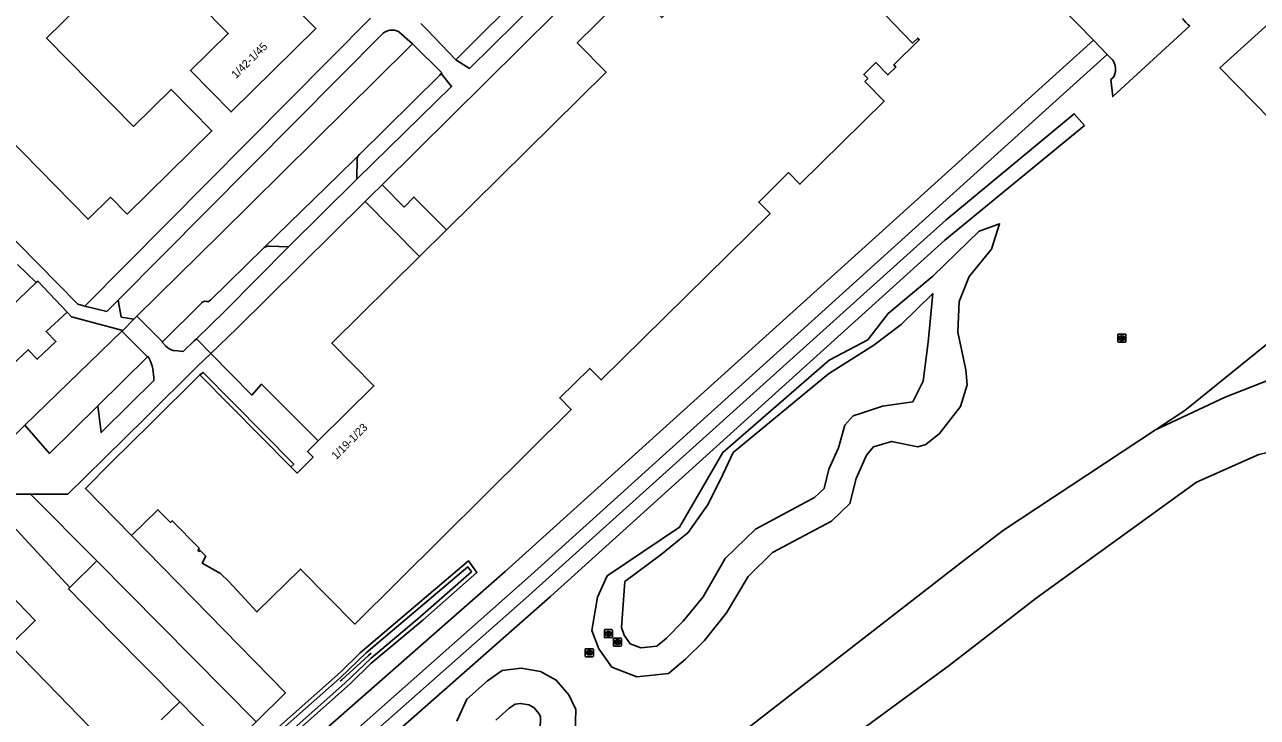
# Model space of a CAD drawing. Extents: x 162791 to 163827, y 385795 to 386523.
# Drawn here: x 162989.1 to 163143.1, y 385940.4 to 386026.9 of the extents above; entities that cross this region are included whole.
import ezdxf

# ---------------------------------------------------------------- set-up
doc = ezdxf.new("R2010")
doc.units = 0
for name, color, linetype in [('IMGEO_Duiker', 7, 'Continuous'), ('IMGEO_Erf', 7, 'Continuous'), ('IMGEO_Grasland_overig', 7, 'Continuous'), ('IMGEO_Groenvoorziening', 7, 'Continuous'), ('IMGEO_Hek', 7, 'Continuous'), ('IMGEO_Loofbos', 7, 'Continuous'), ('IMGEO_Meer_plas_ven_vijver', 7, 'Continuous'), ('IMGEO_Pand', 7, 'Continuous'), ('IMGEO_Pand_nummerreeks', 7, 'Continuous'), ('IMGEO_Parkeervlak_open', 7, 'Continuous'), ('IMGEO_Rijbaan_lokaal_gesloten', 7, 'Continuous'), ('IMGEO_Rijbaan_lokaal_open', 7, 'Continuous'), ('IMGEO_Rioolput', 7, 'Continuous'), ('IMGEO_Rivier', 7, 'Continuous'), ('IMGEO_Terreindeel_open', 7, 'Continuous'), ('IMGEO_Voetpad_halfverhard', 7, 'Continuous'), ('IMGEO_Voetpad_open', 7, 'Continuous'), ('IMGEO_Waterloop', 7, 'Continuous'), ('IMGEO_Woonerf_gesloten', 7, 'Continuous'), ('IMGEO_Woonerf_open', 7, 'Continuous')]:
    doc.layers.add(name, color=color, linetype=linetype)

msp = doc.modelspace()

# ---------------------------------------------------------------- linework, layer by layer
at = {"layer": 'IMGEO_Duiker'}
msp.add_lwpolyline([(163032.39, 385948.39), (163032.06, 385948.09), (163028.71, 385945.05), (163028.51, 385944.87)], dxfattribs=at)
at = {"layer": 'IMGEO_Erf'}
msp.add_lwpolyline([(163029.78, 385944.56), (163016.33, 385932.62), (163015.69, 385932.14), (163014.74, 385932.48), (163014.13, 385933.23), (163028.55, 385946.01), (163031.02, 385948.44), (163044.54, 385959.92), (163045.58, 385958.47), (163038.86, 385952.52), (163032.36, 385947.07), (163029.78, 385944.56)], dxfattribs=at)
at = {"layer": 'IMGEO_Grasland_overig'}
for points in [[(163206.68, 386083.38), (163206.37, 386083.1), (163138.45, 386021.55), (163159.54, 386000), (163159.93, 385999.61)], [(163106.02, 385979.22), (163106.86, 385981.92), (163106.68, 385983.79), (163105.69, 385988.52), (163105.84, 385992.35), (163107.1, 385995.47), (163109.92, 385998.89), (163110.92, 386002.06), (163108.35, 386001.11), (163102.57, 385995.52), (163096.98, 385990.84), (163094.46, 385987.56), (163089.63, 385985), (163076.31, 385973.48), (163070.9, 385964.13), (163061.89, 385958.05), (163060.67, 385955.36), (163059.97, 385951.22), (163060.84, 385948.94), (163062.45, 385946.64), (163065.6, 385945.4), (163069.55, 385945.84), (163071.68, 385947.62), (163074.04, 385949.98), (163076.8, 385953.4), (163079.48, 385957.98), (163082.54, 385960.98), (163089.9, 385964.89), (163092.2, 385967.07), (163092.98, 385970.2), (163094.27, 385973.14), (163095.16, 385974.15), (163097.41, 385974.84), (163100.69, 385974.17), (163101.69, 385974.44), (163103.39, 385975.82), (163106.02, 385979.22)], [(163040.43, 385899.61), (163044.54, 385903.54), (163046.78, 385907.18), (163047.56, 385909.89), (163047.5, 385912), (163047.85, 385913.76), (163049.18, 385914.93), (163052.8, 385917.43), (163058.52, 385922.26), (163075.19, 385935.93), (163079.12, 385938.74), (163105.9, 385959.53), (163111.4, 385963.76), (163130.4, 385976.29)], [(163004.99, 385938.91), (163001.1, 385935.13), (162993.27, 385943.2), (162987.27, 385949.39), (162990.42, 385952.45), (162984.93, 385958.1), (162984.82, 385958.21), (162984.99, 385958.38), (162983.58, 385959.83), (162983.68, 385959.93), (162982.32, 385961.34), (162982.74, 385961.74), (162981.36, 385963.16), (162980.71, 385967.36)], [(163057.86, 385938.35), (163057.95, 385941.32), (163057.1, 385943.18), (163055.52, 385945.02), (163053.56, 385946.09), (163051.15, 385946.52), (163048.76, 385946.2), (163046.92, 385944.94), (163044.36, 385942.63), (163043.1, 385939.87)]]:
    msp.add_lwpolyline(points, dxfattribs=at)
at = {"layer": 'IMGEO_Groenvoorziening'}
msp.add_lwpolyline([(162986.64, 385968.27), (162986.63, 385966.43), (162987.09, 385965.94), (162986.55, 385965.43), (162994.73, 385956.59)], dxfattribs=at)
at = {"layer": 'IMGEO_Hek'}
msp.add_lwpolyline([(163159.93, 385999.61), (163159.54, 386000), (163138.45, 386021.55), (163206.37, 386083.1), (163209.63, 386080.99), (163212.23, 386083.36)], dxfattribs=at)
at = {"layer": 'IMGEO_Loofbos'}
for points in [[(163159.93, 385999.61), (163134.06, 385978.71), (163130.4, 385976.29)], [(163130.4, 385976.29), (163139.09, 385980.37), (163147.79, 385983.78), (163156.15, 385986.14), (163163.03, 385986.86), (163172.38, 385986.5)]]:
    msp.add_lwpolyline(points, dxfattribs=at)
at = {"layer": 'IMGEO_Meer_plas_ven_vijver'}
for points in [[(163063.65, 385951.58), (163064.1, 385957.33), (163068.63, 385960.73), (163071.98, 385963.45), (163074.43, 385966.89), (163076.06, 385970.15), (163077.61, 385973.44), (163089.53, 385983.31), (163095.2, 385986.88), (163098.61, 385989.48), (163102.55, 385993.33), (163102, 385987.26), (163101.37, 385982.37), (163100.06, 385979.79), (163096.29, 385979.25), (163093.67, 385978.39), (163092.62, 385978.05), (163091.57, 385976.87), (163090.77, 385974.04), (163089.59, 385971.36), (163088.99, 385968.94), (163087.8, 385967.82), (163080.41, 385963.89), (163076.64, 385960.19), (163073.86, 385955.43), (163071.38, 385952.37), (163069.27, 385950.25), (163068.09, 385949.26), (163066.08, 385949.04), (163064.75, 385949.56), (163064.01, 385950.62), (163063.65, 385951.58)], [(163047.95, 385939.99), (163049.63, 385941.5), (163050.37, 385942.01), (163051.05, 385942.1), (163052.1, 385941.92), (163052.73, 385941.57), (163053.39, 385940.81), (163053.56, 385940.43), (163053.51, 385938.8)]]:
    msp.add_lwpolyline(points, dxfattribs=at)
at = {"layer": 'IMGEO_Pand'}
for points in [[(162999.83, 386005.36), (163001.89, 386003.26), (163012.48, 386013.66), (163007.39, 386018.84), (163002.69, 386014.21), (162991.83, 386025.26), (163003.66, 386036.89), (163014.52, 386025.84), (163009.81, 386021.21), (163014.89, 386016.04), (163025.48, 386026.44), (163023.41, 386028.54), (163026.22, 386031.3), (163011.87, 386045.9), (163011, 386045.05), (163005.67, 386050.48), (163006.53, 386051.33), (162992.18, 386065.93), (162989.38, 386063.17), (162987.31, 386065.27)], [(163002.45, 385963.07), (163005.73, 385966.3), (163007.21, 385964.8), (163007.3, 385964.7), (163007.53, 385964.93), (163010.89, 385961.52), (163010.77, 385961.2), (163010.86, 385961.1), (163011, 385961.22), (163011.72, 385960.51), (163011.25, 385959.63), (163013.58, 385958.35), (163014.59, 385957.35), (163018.12, 385953.54), (163023.56, 385958.89), (163030.33, 385952.01), (163057.39, 385978.84), (163055.96, 385980.29), (163059.71, 385983.98), (163061.14, 385982.53), (163082.23, 386003.32), (163080.81, 386004.77), (163084.54, 386008.45), (163085.96, 386007), (163096.49, 386017.37), (163094.08, 386019.83), (163094.44, 386020.19), (163093.94, 386020.7), (163095.45, 386022.19), (163096.96, 386020.66), (163097.95, 386021.63), (163097.69, 386021.9), (163100.88, 386025.06), (163100.68, 386025.26), (163100.05, 386024.64), (163081.98, 386043.39)], [(163077.49, 386036.5), (163068.7, 386027.82), (163065.05, 386031.48), (163058.14, 386024.66), (163061.75, 386021), (163041.79, 386001.29)], [(162982.68, 386017.21), (162997.02, 386002.61), (162999.83, 386005.36)], [(163041.79, 386001.29), (163038.44, 385997.98)], [(163038.44, 385997.98), (163027.46, 385987.14), (163032.74, 385981.78), (163025.76, 385974.9)], [(162994.39, 385991), (162991.77, 385988.59), (162992.99, 385987.33), (162990.67, 385985.11), (162989.54, 385986.3), (162986.71, 385983.61), (162983, 385987.51), (162990.54, 385994.69)], [(162990.54, 385994.69), (162990.72, 385994.86), (162994.39, 385991)], [(163010.98, 385983.18), (163004.84, 385977.1), (162999.89, 385972.2), (162996.67, 385968.98), (163002.45, 385963.07)], [(163022.35, 385971.68), (163010.98, 385983.18)], [(163025.76, 385974.9), (163024.42, 385973.58), (163025.12, 385972.86), (163023.14, 385970.88), (163022.35, 385971.68)]]:
    msp.add_lwpolyline(points, dxfattribs=at)
at = {"layer": 'IMGEO_Parkeervlak_open'}
for points in [[(163030.81, 386010.6), (163030.48, 386010.27), (163028.35, 386008.16), (163019.02, 385999.1)], [(163030.58, 386007.63), (163030.63, 386010.17), (163030.64, 386010.24), (163030.66, 386010.31), (163030.68, 386010.37), (163030.7, 386010.43), (163030.73, 386010.49), (163030.77, 386010.55), (163030.81, 386010.6)], [(163022.06, 385999.15), (163030.58, 386007.63)], [(163022.06, 385999.15), (163019.64, 385999.26)], [(162994.73, 385956.59), (162998.1, 385959.9)], [(163008.47, 385942.28), (163000, 385950.88), (162994.55, 385956.41), (162994.73, 385956.59)], [(163018.03, 385939.78), (163014.44, 385936.23), (163008.47, 385942.28)]]:
    msp.add_lwpolyline(points, dxfattribs=at)
msp.add_arc((163019.59, 385998.18), 1.08, 87.2247, 121.9721, dxfattribs=at)
at = {"layer": 'IMGEO_Rijbaan_lokaal_gesloten'}
for points in [[(163088.02, 386060.38), (163122.64, 386025)], [(163124.83, 386020.08), (163125.06, 386017.94), (163134.7, 386026.78)], [(163122.64, 386025), (163124.37, 386023.23)], [(163124.37, 386023.23), (163124.87, 386022.73)]]:
    msp.add_lwpolyline(points, dxfattribs=at)
for centre, radius, start, end in [((163136.2, 386029.17), 2.82, 211.1483, 237.9221), ((163123.26, 386021.31), 2.14, 353.6122, 41.3992), ((163124.06, 386021.17), 1.33, 305.2318, 355.5793)]:
    msp.add_arc(centre, radius, start, end, dxfattribs=at)
at = {"layer": 'IMGEO_Rijbaan_lokaal_open'}
for points in [[(162989.82, 385968.26), (162994.48, 385968.27), (162999.07, 385972.74), (163004.18, 385977.79), (163010.64, 385984.19), (163012.36, 385985.85)], [(163012.36, 385985.85), (163017.47, 385980.63), (163018.7, 385982.02), (163025.76, 385974.9)], [(163010.98, 385983.18), (163011.38, 385983.48), (163022.72, 385972), (163022.35, 385971.68)], [(162998.1, 385959.9), (162989.82, 385968.26)], [(163002.45, 385963.07), (163021.68, 385943.41), (163018.03, 385939.78)], [(162998.1, 385959.9), (163018.03, 385939.78)]]:
    msp.add_lwpolyline(points, dxfattribs=at)
at = {"layer": 'IMGEO_Rioolput'}
for p, q in [((163125.77, 385988.26), (163126.62, 385988.26)), ((163125.69, 385987.33), (163125.69, 385988.18)), ((163126.62, 385987.25), (163125.77, 385987.25)), ((163126.18, 385988.03), (163126.21, 385988.03)), ((163126.2, 385987.48), (163126.18, 385987.48)), ((163126.69, 385988.18), (163126.69, 385987.33)), ((163061.53, 385950.39), (163061.53, 385951.25)), ((163061.61, 385951.32), (163062.46, 385951.32)), ((163062.53, 385951.25), (163062.53, 385950.39)), ((163062.46, 385950.32), (163061.61, 385950.32)), ((163062.02, 385951.1), (163062.04, 385951.1)), ((163062.04, 385950.54), (163062.02, 385950.54)), ((163062.66, 385949.34), (163062.66, 385950.19)), ((163062.73, 385950.26), (163063.59, 385950.26)), ((163063.15, 385950.04), (163063.17, 385950.04)), ((163063.66, 385950.19), (163063.66, 385949.34)), ((163059.14, 385948), (163059.14, 385948.86)), ((163059.22, 385948.93), (163060.07, 385948.93)), ((163059.63, 385948.71), (163059.66, 385948.71)), ((163059.65, 385948.15), (163059.63, 385948.15)), ((163060.15, 385948.86), (163060.15, 385948)), ((163063.59, 385949.26), (163062.73, 385949.26)), ((163063.17, 385949.48), (163063.15, 385949.48)), ((163060.07, 385947.93), (163059.22, 385947.93))]:
    msp.add_line(p, q, dxfattribs=at)
for points in [[(163125.77, 385988.26), (163126.62, 385988.26)], [(163125.69, 385987.33), (163125.69, 385988.18)], [(163126.62, 385987.25), (163125.77, 385987.25)], [(163126.28, 385987.95), (163126.03, 385987.95), (163126.03, 385987.55)], [(163126.03, 385987.55), (163126.15, 385987.55), (163126.15, 385987.72), (163126.16, 385987.72)], [(163126.21, 385987.87), (163126.15, 385987.87), (163126.15, 385987.79)], [(163126.15, 385987.79), (163126.2, 385987.79)], [(163126.21, 385987.69), (163126.28, 385987.55), (163126.42, 385987.55), (163126.36, 385987.68)], [(163126.69, 385988.18), (163126.69, 385987.33)], [(163061.53, 385950.39), (163061.53, 385951.25)], [(163061.61, 385951.32), (163062.46, 385951.32)], [(163062.53, 385951.25), (163062.53, 385950.39)], [(163062.46, 385950.32), (163061.61, 385950.32)], [(163062.12, 385951.02), (163061.87, 385951.02), (163061.87, 385950.62)], [(163061.87, 385950.62), (163061.99, 385950.62), (163061.99, 385950.78), (163062, 385950.78)], [(163062.05, 385950.94), (163061.99, 385950.94), (163061.99, 385950.86)], [(163061.99, 385950.86), (163062.04, 385950.86)], [(163062.05, 385950.75), (163062.12, 385950.62), (163062.26, 385950.62), (163062.2, 385950.75)], [(163062.66, 385949.34), (163062.66, 385950.19)], [(163062.73, 385950.26), (163063.59, 385950.26)], [(163063.25, 385949.96), (163063, 385949.96), (163063, 385949.56)], [(163063, 385949.56), (163063.12, 385949.56), (163063.12, 385949.73), (163063.13, 385949.73)], [(163063.18, 385949.88), (163063.12, 385949.88), (163063.12, 385949.8)], [(163063.12, 385949.8), (163063.17, 385949.8)], [(163063.18, 385949.7), (163063.25, 385949.56), (163063.39, 385949.56), (163063.32, 385949.69)], [(163063.66, 385950.19), (163063.66, 385949.34)], [(163059.14, 385948), (163059.14, 385948.86)], [(163059.22, 385948.93), (163060.07, 385948.93)], [(163059.73, 385948.63), (163059.48, 385948.63), (163059.48, 385948.23)], [(163059.48, 385948.23), (163059.61, 385948.23), (163059.61, 385948.39), (163059.62, 385948.39)], [(163059.66, 385948.55), (163059.61, 385948.55), (163059.61, 385948.47)], [(163059.61, 385948.47), (163059.66, 385948.47)], [(163059.66, 385948.36), (163059.73, 385948.23), (163059.87, 385948.23), (163059.81, 385948.36)], [(163060.15, 385948.86), (163060.15, 385948)], [(163063.59, 385949.26), (163062.73, 385949.26)], [(163060.07, 385947.93), (163059.22, 385947.93)]]:
    msp.add_lwpolyline(points, dxfattribs=at)
for centre, radius, start, end in [((163125.77, 385988.18), 0.0765, 91.552, 178.448), ((163125.77, 385988.18), 0.0765, 91.552, 178.448), ((163126.62, 385988.18), 0.0765, 1.552, 88.448), ((163126.62, 385988.18), 0.0765, 1.552, 88.448), ((163125.77, 385987.33), 0.0765, 181.552, 268.448), ((163125.77, 385987.33), 0.0765, 181.552, 268.448), ((163126.16, 385987.66), 0.0533, 26.0293, 88.6989), ((163126.19, 385987.98), 0.19, 274.7715, 282.9687), ((163126.21, 385987.78), 0.0964, 77.0061, 93.1865), ((163126.23, 385987.83), 0.0378, 276.6634, 79.6772), ((163126.28, 385987.84), 0.109, 350.3612, 89.416), ((163126.28, 385987.84), 0.112, 277.5842, 350.9817), ((163126.26, 385987.63), 0.108, 29.5134, 73.7905), ((163126.62, 385987.33), 0.0765, 271.552, 358.448), ((163126.62, 385987.33), 0.0765, 271.552, 358.448), ((163061.61, 385951.24), 0.0765, 91.552, 178.448), ((163061.61, 385951.24), 0.0765, 91.552, 178.448), ((163062.46, 385951.24), 0.0765, 1.552, 88.448), ((163062.46, 385951.24), 0.0765, 1.552, 88.448), ((163061.61, 385950.39), 0.0765, 181.552, 268.448), ((163061.61, 385950.39), 0.0765, 181.552, 268.448), ((163062, 385950.73), 0.0533, 26.0293, 88.6989), ((163062.03, 385951.05), 0.19, 274.7715, 282.9687), ((163062.05, 385950.84), 0.0964, 77.0061, 93.1865), ((163062.07, 385950.9), 0.0378, 276.6634, 79.6772), ((163062.12, 385950.91), 0.109, 350.3612, 89.416), ((163062.12, 385950.91), 0.112, 277.5842, 350.9817), ((163062.1, 385950.69), 0.108, 29.5134, 73.7905), ((163062.46, 385950.39), 0.0765, 271.552, 358.448), ((163062.46, 385950.39), 0.0765, 271.552, 358.448), ((163062.74, 385950.19), 0.0765, 91.552, 178.448), ((163062.74, 385950.19), 0.0765, 91.552, 178.448), ((163063.13, 385949.67), 0.0533, 26.0293, 88.6989), ((163063.16, 385949.99), 0.19, 274.7715, 282.9687), ((163063.18, 385949.79), 0.0964, 77.0061, 93.1865), ((163063.2, 385949.84), 0.0378, 276.6634, 79.6772), ((163063.25, 385949.85), 0.109, 350.3612, 89.416), ((163063.25, 385949.85), 0.112, 277.5842, 350.9817), ((163063.23, 385949.64), 0.108, 29.5134, 73.7905), ((163063.58, 385950.19), 0.0765, 1.552, 88.448), ((163063.58, 385950.19), 0.0765, 1.552, 88.448), ((163059.22, 385948.85), 0.0765, 91.552, 178.448), ((163059.22, 385948.85), 0.0765, 91.552, 178.448), ((163059.61, 385948.34), 0.0533, 26.0293, 88.6989), ((163059.66, 385948.45), 0.0964, 77.0061, 93.1865), ((163059.64, 385948.66), 0.19, 274.7715, 282.9687), ((163059.68, 385948.51), 0.0378, 276.6634, 79.6772), ((163059.73, 385948.52), 0.109, 350.3612, 89.416), ((163059.73, 385948.52), 0.112, 277.5842, 350.9817), ((163059.71, 385948.3), 0.108, 29.5134, 73.7905), ((163060.07, 385948.85), 0.0765, 1.552, 88.448), ((163060.07, 385948.85), 0.0765, 1.552, 88.448), ((163062.74, 385949.34), 0.0765, 181.552, 268.448), ((163062.74, 385949.34), 0.0765, 181.552, 268.448), ((163063.58, 385949.34), 0.0765, 271.552, 358.448), ((163063.58, 385949.34), 0.0765, 271.552, 358.448), ((163059.22, 385948.01), 0.0765, 181.552, 268.448), ((163059.22, 385948.01), 0.0765, 181.552, 268.448), ((163060.07, 385948.01), 0.0765, 271.552, 358.448), ((163060.07, 385948.01), 0.0765, 271.552, 358.448)]:
    msp.add_arc(centre, radius, start, end, dxfattribs=at)
for centre, major_axis, ratio, start_param, end_param in [((163126.18, 385987.75), (-0.387, 0.002), 0.722429, 4.712389, 7.853982), ((163126.2, 385987.75), (-0.39, 0.002), 0.717154, 1.570796, 4.712389), ((163062.02, 385950.82), (-0.387, 0.002), 0.722429, 4.712389, 7.853982), ((163062.04, 385950.82), (-0.39, 0.002), 0.717154, 1.570796, 4.712389), ((163063.15, 385949.76), (-0.387, 0.002), 0.722429, 4.712389, 7.853982), ((163063.17, 385949.76), (-0.39, 0.002), 0.717154, 1.570796, 4.712389), ((163059.63, 385948.43), (-0.387, 0.002), 0.722429, 4.712389, 7.853982), ((163059.66, 385948.43), (-0.39, 0.002), 0.717154, 1.570796, 4.712389)]:
    msp.add_ellipse(centre, major_axis=major_axis, ratio=ratio, start_param=start_param, end_param=end_param, dxfattribs=at)
at = {"layer": 'IMGEO_Rivier'}
msp.add_lwpolyline([(163154.69, 385975.39), (163149.67, 385974.61), (163143.32, 385973.23), (163135.53, 385969.74), (163115.47, 385955.24), (163104.61, 385946.82), (163102.59, 385945.33), (163085.37, 385932.7), (163077.4, 385926.76), (163061.31, 385913.73), (163042.26, 385896.86), (163040.43, 385899.61)], dxfattribs=at)
at = {"layer": 'IMGEO_Terreindeel_open'}
msp.add_lwpolyline([(163008.47, 385942.28), (163006.16, 385940.04)], dxfattribs=at)
at = {"layer": 'IMGEO_Voetpad_halfverhard'}
for points in [[(163017.32, 385930.66), (163017.73, 385931.02), (163049.15, 385958.58), (163094.98, 386000), (163117.54, 386020.39), (163122.64, 386025)], [(163016.59, 385921.55), (163015.1, 385924.93), (163016.55, 385926.06), (163019.49, 385929), (163052.33, 385958.14), (163098.66, 386000), (163119.27, 386018.62), (163124.37, 386023.23)]]:
    msp.add_lwpolyline(points, dxfattribs=at)
at = {"layer": 'IMGEO_Voetpad_open'}
for points in [[(162996.59, 385991.77), (162995.75, 385991.99), (162975.95, 386012.1), (162974.57, 386010.75)], [(163031.64, 386004.84), (163032.29, 386005.49), (163033.75, 386006.93)], [(163041.79, 386001.29), (163037.72, 386005.38), (163036.49, 386004.14), (163033.75, 386006.93)], [(163038.44, 385997.98), (163031.64, 386004.84)], [(162988.2, 385996.97), (162990.54, 385994.69)], [(163000.76, 385992.51), (162999.35, 385991.1), (162996.59, 385991.77)], [(163000.76, 385992.51), (163001.16, 385990.39), (163002.72, 385990.11)], [(162994.39, 385991), (162994.95, 385990.42), (163001.34, 385988.73)], [(163001.34, 385988.73), (163002.72, 385990.11)]]:
    msp.add_lwpolyline(points, dxfattribs=at)
at = {"layer": 'IMGEO_Waterloop'}
for points in [[(163054.79, 385955.47), (163104.07, 386000), (163121.52, 386014.34), (163120.25, 386015.8), (163104.22, 386002.53), (163101.4, 386000), (163051.73, 385955.26), (163025.72, 385932.3), (163026.92, 385930.93), (163054.79, 385955.47)], [(163032.39, 385947.75), (163038.53, 385952.9), (163044.91, 385958.54), (163044.45, 385959.18), (163031.76, 385948.4), (163028.5, 385945.29), (163014.82, 385933.18), (163015.05, 385932.9), (163015.61, 385932.7), (163016, 385932.99), (163029.08, 385944.61), (163032.39, 385947.75)]]:
    msp.add_lwpolyline(points, dxfattribs=at)
at = {"layer": 'IMGEO_Woonerf_gesloten'}
for points in [[(163033.75, 386006.93), (163059.67, 386032.61), (163072.63, 386045.31)], [(163061.92, 386038.49), (163044.67, 386021.48), (163042.97, 386022.55)], [(163032.29, 386027.77), (162996.59, 385991.77)], [(163042.97, 386022.55), (163039.34, 386026.32), (163038.58, 386027.1)], [(163037.57, 386024.55), (163037.56, 386024.56), (163035.84, 386026.06), (163035.71, 386026.12), (163035.57, 386026.18), (163035.43, 386026.22), (163035.29, 386026.25), (163035.14, 386026.27), (163034.99, 386026.27), (163034.84, 386026.26), (163034.7, 386026.24), (163034.55, 386026.21), (163034.41, 386026.16), (163034.28, 386026.1), (163034.15, 386026.03), (163034.02, 386025.95), (163033.9, 386025.86), (163000.76, 385992.51)], [(163037.57, 386024.55), (163041.21, 386020.9), (163041.15, 386020.84)], [(163041.15, 386020.84), (163042.44, 386019.2), (163030.58, 386007.63)], [(163012.36, 385985.85), (163015.62, 385988.98), (163031.64, 386004.84)], [(163010.56, 385987.68), (163014.14, 385991.17), (163022.06, 385999.15)], [(163002.72, 385990.11), (163003.11, 385990.49)], [(163003.11, 385990.49), (163006.31, 385987.31)], [(163001.24, 385988.64), (163001.34, 385988.73)], [(163004.45, 385985.42), (163001.24, 385988.64)], [(163006.31, 385987.31), (163006.26, 385987.26), (163006.74, 385986.76)], [(163007.83, 385986.19), (163008.88, 385986.1), (163010.28, 385987.4), (163010.56, 385987.68)], [(163010.56, 385987.68), (163012.36, 385985.85)], [(163004.62, 385985.28), (163004.49, 385985.47), (163004.45, 385985.42)], [(162998.23, 385979.29), (162998.66, 385975.96), (163002.19, 385979.46), (163005.23, 385982.48)], [(162989.09, 385976.86), (162992.2, 385973.35), (162998.23, 385979.29)], [(162987.84, 385975.64), (162989.09, 385976.86)], [(162986.64, 385968.27), (162989.82, 385968.26)]]:
    msp.add_lwpolyline(points, dxfattribs=at)
for centre, radius, start, end in [((163008.1, 385988.07), 1.9, 223.8361, 261.8307), ((162999.41, 385982.67), 5.82, 358.0925, 26.6052)]:
    msp.add_arc(centre, radius, start, end, dxfattribs=at)
at = {"layer": 'IMGEO_Woonerf_open'}
for points in [[(163042.97, 386022.55), (163052.2, 386031.81), (163058.92, 386038.31), (163058.97, 386038.36)], [(163003.11, 385990.49), (163013.51, 386000.75), (163037.1, 386024.08), (163037.57, 386024.55)], [(163041.15, 386020.84), (163040.96, 386020.64), (163030.91, 386010.7), (163030.86, 386010.65), (163030.81, 386010.6)], [(163019.02, 385999.1), (163012.3, 385992.49)], [(163011.21, 385992.17), (163006.31, 385987.31)], [(162989.09, 385976.86), (163001.24, 385988.64)], [(163004.45, 385985.42), (162998.23, 385979.29)]]:
    msp.add_lwpolyline(points, dxfattribs=at)
for centre, radius, start, end in [((163011.65, 385991.76), 0.6, 77.9532, 137.8277), ((163011.92, 385992.89), 0.559, 255.4913, 313.5548)]:
    msp.add_arc(centre, radius, start, end, dxfattribs=at)

# ---------------------------------------------------------------- texts
at = {"layer": 'IMGEO_Pand_nummerreeks'}
for s, rotation, p in [('1/42-1/45', 44.7111, (163015.5, 386020.14)), ('1/19-1/23', 44.8741, (163028.02, 385972.51))]:
    msp.add_text(s, height=1, rotation=rotation, dxfattribs=at).set_placement(p)

doc.saveas('drawing.dxf')
